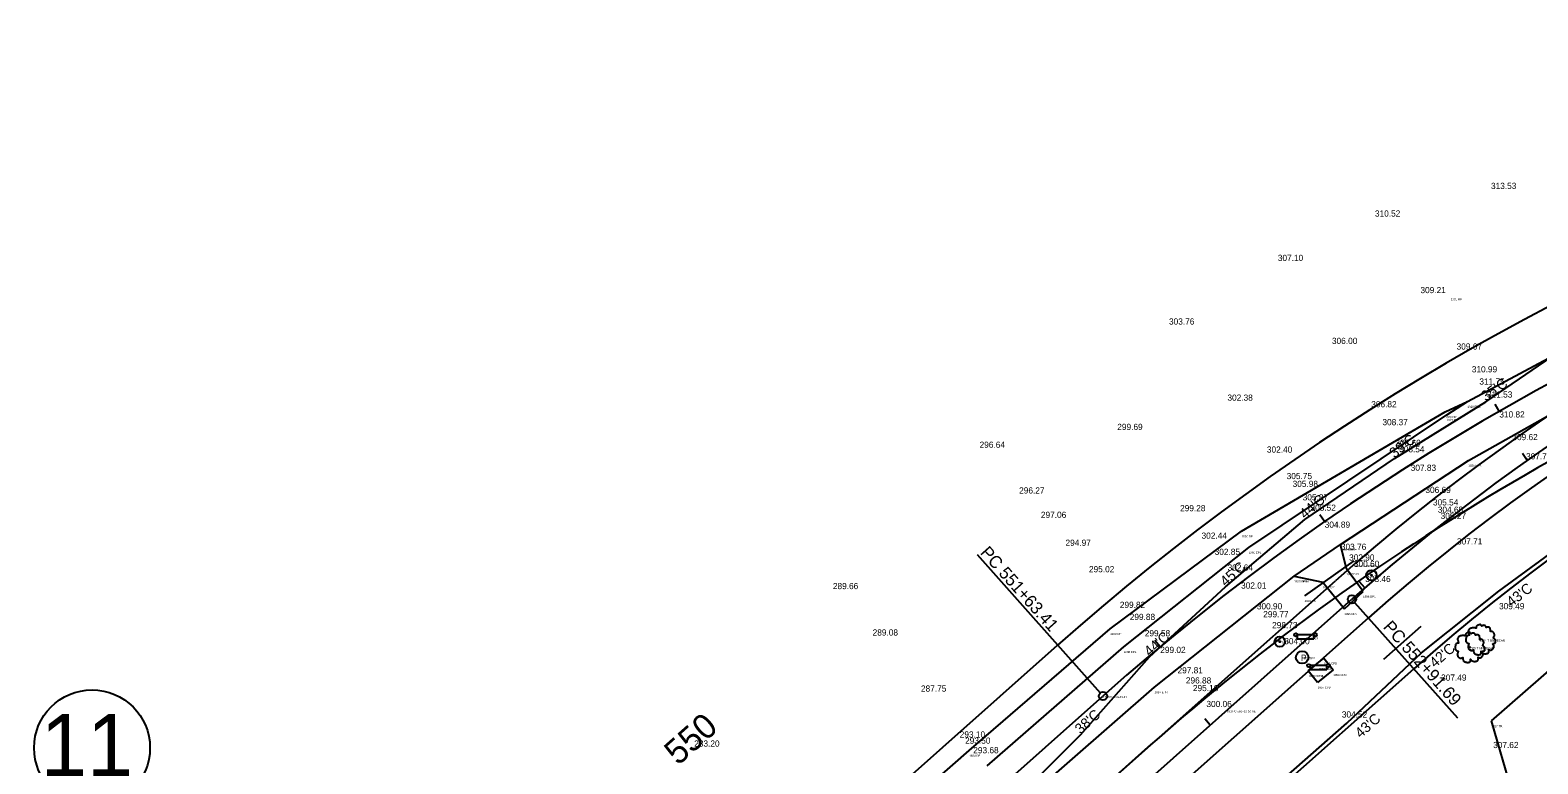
# Model space of a CAD drawing. Extents: x 49683 to 58852, y 49525 to 54803.
# Drawn here: x 55511 to 56241, y 53749 to 54104 of the extents above; entities that cross this region are included whole.
import ezdxf

# ---------------------------------------------------------------- set-up
doc = ezdxf.new("R2010")
doc.units = 0
for name, color, linetype in [('Level 1', 7, 'Continuous'), ('Level 11', 7, 'Continuous'), ('Level 12', 7, 'Continuous'), ('Level 13', 7, 'Continuous'), ('Level 18', 7, 'Continuous'), ('Level 19', 7, 'Continuous'), ('Level 20', 7, 'Continuous'), ('Level 21', 7, 'Continuous'), ('Level 25', 7, 'Continuous'), ('Level 3', 7, 'Continuous'), ('Level 32', 7, 'Continuous'), ('Level 33', 7, 'Continuous'), ('Level 34', 7, 'Continuous'), ('Level 48', 7, 'Continuous'), ('Level 51', 7, 'Continuous'), ('Level 53', 7, 'Continuous'), ('Level 56', 7, 'Continuous'), ('Level 58', 7, 'Continuous'), ('Level 59', 7, 'Continuous'), ('Level 6', 7, 'Continuous'), ('Level 61', 7, 'Continuous'), ('Level 62', 7, 'Continuous'), ('Level 8', 7, 'Continuous'), ('Level 9', 7, 'Continuous')]:
    doc.layers.add(name, color=color, linetype=linetype)

# ---------------------------------------------------------------- blocks, each defined once
blk = doc.blocks.new('IP')
at = {"layer": 'Level 12'}
for radius in [2.5, 0.25]:
    blk.add_circle((0, 0), radius, dxfattribs=at)
blk = doc.blocks.new('TBX')
at = {"layer": 'Level 9'}
for p, q in [((3.99, 1.14), (-4.01, 1.14)), ((-4.01, 1.14), (-4.01, -0.82)), ((3.99, -0.82), (3.99, 1.14)), ((-4.01, -0.82), (3.99, -0.82))]:
    blk.add_line(p, q, dxfattribs=at)
for centre in [(-4.76, 1.14), (4.74, 1.14)]:
    blk.add_circle(centre, 0.75, dxfattribs=at)
blk = doc.blocks.new('TPP')
at = {"layer": 'Level 9'}
blk.add_circle((0, 0), 3, dxfattribs=at)
blk.add_text('P', height=3, dxfattribs=at).set_placement((-0.59, -1.73))
blk = doc.blocks.new('T1')
at = {"layer": 'Level 11'}
for centre, radius in [((0, 0), 0.25), ((-0.01, -0.02), 0.0001)]:
    blk.add_circle(centre, radius, dxfattribs=at)
for points in [[(0.13, 7.17), (-0.17, 7.19), (-0.49, 7.09), (-0.74, 6.99), (-0.97, 6.92), (-1.19, 6.82), (-1.49, 6.64), (-1.72, 6.44), (-1.84, 6.19), (-1.89, 5.97), (-1.94, 5.69), (-1.94, 5.52), (-2.07, 5.49), (-2.22, 5.52), (-2.47, 5.59), (-2.72, 5.59), (-2.97, 5.59), (-3.32, 5.57), (-3.67, 5.57), (-3.94, 5.52), (-4.27, 5.47), (-4.64, 5.34), (-4.99, 5.22), (-5.29, 4.97), (-5.54, 4.49), (-5.67, 4.14), (-5.82, 3.89), (-5.67, 3.44), (-5.49, 3.09), (-5.47, 2.89), (-5.39, 2.47), (-5.29, 2.24), (-5.17, 2.04), (-5.24, 2.02), (-5.62, 1.97), (-5.92, 1.87), (-6.34, 1.64), (-6.57, 1.42), (-6.67, 1.09), (-6.69, 0.75), (-6.79, 0.55), (-6.87, 0.27), (-6.89, 0.2), (-6.94, -0.13), (-6.84, -0.58), (-6.82, -0.93), (-6.69, -1.15), (-6.54, -1.33), (-6.37, -1.58), (-5.97, -1.8), (-5.64, -1.9), (-5.44, -1.93), (-5.62, -2.43), (-5.67, -2.78), (-5.79, -3.18), (-5.79, -3.25), (-5.84, -3.73), (-5.69, -4.05), (-5.62, -4.43), (-5.44, -4.65), (-5.17, -4.95), (-4.84, -5.18), (-4.34, -5.3), (-3.94, -5.28), (-3.37, -5.1), (-3.12, -5.03), (-3.14, -5.2), (-3.12, -5.58), (-3.12, -6), (-2.97, -6.33), (-2.87, -6.6), (-2.72, -6.85), (-2.39, -7.08), (-1.99, -7.15), (-1.57, -7.3), (-1.12, -7.38), (-0.62, -7.4), (-0.02, -7.25), (0.26, -7.13), (0.36, -6.95), (0.56, -6.58), (0.51, -6.35), (0.53, -5.75), (0.63, -5.93), (0.81, -6.28), (1.31, -6.58), (1.71, -6.75), (2.18, -6.9), (2.48, -6.98), (2.96, -6.9), (3.33, -6.83), (3.71, -6.7), (4.01, -6.43), (4.18, -6.15), (4.23, -5.88), (4.31, -5.5), (4.36, -5.33)], [(4.36, -5.33), (4.28, -5.15), (4.23, -4.9), (4.31, -4.93), (4.48, -4.98), (4.75, -5.1), (4.98, -5.18), (5.3, -5.15), (5.58, -5.05), (6.03, -4.78), (6.3, -4.3), (6.58, -3.9), (6.65, -3.58), (6.6, -3.35), (6.58, -2.85), (6.38, -2.6), (6.33, -2.48), (6.23, -2.08), (6.3, -2.03), (6.58, -1.98), (6.95, -1.85), (7.23, -1.73), (7.45, -1.55), (7.53, -1.33), (7.5, -0.93), (7.55, -0.53), (7.48, -0.38), (7.38, -0.23), (7.3, -0.03), (7.15, 0.12), (7.05, 0.27), (6.95, 0.37), (6.83, 0.52), (6.65, 0.65), (6.5, 0.7), (6.45, 0.85), (6.6, 1.04), (6.65, 1.14), (6.68, 1.37), (6.9, 1.72), (6.95, 2.12), (6.9, 2.54), (6.85, 2.82), (6.7, 3.09), (6.5, 3.34), (6.38, 3.52), (6.2, 3.64), (5.88, 3.77), (5.63, 3.82), (5.28, 3.82), (5.08, 3.87), (5.1, 3.92), (5.1, 4.07), (5.1, 4.34), (5.03, 4.79), (4.88, 5.29), (4.88, 5.32), (4.78, 5.57), (4.56, 5.77), (4.38, 5.87), (4.18, 5.99), (3.93, 6.02), (3.63, 6.02), (3.36, 5.97), (3.16, 5.87), (2.98, 5.74), (2.91, 5.89), (2.81, 6.19), (2.76, 6.34), (2.61, 6.52), (2.38, 6.72), (1.93, 6.84), (1.31, 6.77), (1.01, 6.57), (0.86, 6.39), (0.81, 6.52), (0.61, 6.72), (0.51, 6.89), (0.33, 7.02), (0.18, 7.12), (0.08, 7.17)]]:
    blk.add_spline(points, degree=3, dxfattribs=at)

msp = doc.modelspace()

# ---------------------------------------------------------------- linework, layer by layer
at = {"layer": 'Level 1'}
for p, q in [((56222.17, 53919.48), (56220.18, 53922.95)), ((56137.67, 53866.06), (56135.39, 53869.34)), ((55969.5, 53850.14), (56029.09, 53783.1)), ((56058.16, 53805.47), (56055.59, 53808.55)), ((55534.58, 53340.86), (56030.42, 53781.6))]:
    msp.add_line(p, q, dxfattribs=at)
msp.add_circle((56030.42, 53781.6), 2, dxfattribs=at)
msp.add_arc((56791.72, 52925.13), 1145.92, 83.49443, 131.63333, dxfattribs=at)
at = {"layer": 'Level 11'}
for p, q in [((56218.32, 53769.53), (56251.21, 53798.33)), ((56228.2, 53735.68), (56218.32, 53769.53))]:
    msp.add_line(p, q, dxfattribs=at)
at = {"layer": 'Level 13'}
for p, q in [((55512.66, 53365.53), (56008.5, 53806.27)), ((55556.51, 53316.2), (56052.34, 53756.94))]:
    msp.add_line(p, q, dxfattribs=at)
for radius, start in [(1178.92, 86.60044), (1112.92, 108.44495)]:
    msp.add_arc((56791.72, 52925.13), radius, start, 131.63335, dxfattribs=at)
at = {"layer": 'Level 18'}
for p, q in [((56215.63, 53924.12), (56258.38, 53953.39)), ((56171.42, 53896.57), (56215.63, 53924.12)), ((56128.15, 53867.07), (56171.42, 53896.57)), ((56089.77, 53834.41), (56128.15, 53867.07)), ((56221.89, 53832.37), (56260.4, 53860.66)), ((56052.99, 53800.53), (56089.77, 53834.41)), ((56184.48, 53802.58), (56221.89, 53832.37)), ((56019.54, 53762.9), (56052.99, 53800.53)), ((56148.42, 53768.43), (56184.48, 53802.58)), ((56110.9, 53735.37), (56148.42, 53768.43)), ((55984.18, 53727.42), (56019.54, 53762.9))]:
    msp.add_line(p, q, dxfattribs=at)
at = {"layer": 'Level 19'}
for p, q in [((56235.67, 53895.71), (56233.36, 53898.98)), ((56157.09, 53833.94), (56154.45, 53836.95)), ((54181.77, 52078.16), (56150.85, 53828.45)), ((56152.18, 53826.95), (56201.86, 53771.06)), ((56082.32, 53767.53), (56079.66, 53770.52))]:
    msp.add_line(p, q, dxfattribs=at)
msp.add_circle((56150.85, 53828.45), 2, dxfattribs=at)
msp.add_arc((56791.96, 53107.19), 965, 83.49443, 131.63337, dxfattribs=at)
at = {"layer": 'Level 20'}
for p, q in [((55390.95, 53169.04), (56142.88, 53837.41)), ((55400.37, 53145.3), (56158.82, 53819.48))]:
    msp.add_line(p, q, dxfattribs=at)
for radius, start, end in [(977, 84.11358, 131.63331), (953, 83.49443, 131.63337)]:
    msp.add_arc((56791.96, 53107.19), radius, start, end, dxfattribs=at)
at = {"layer": 'Level 25'}
msp.add_circle((55541.4, 53756.52), 28.04, dxfattribs=at)
at = {"layer": 'Level 3'}
for p, q in [((56206.74, 53924.16), (56272.68, 53959.54)), ((56207.19, 53895.72), (56282.12, 53937.76)), ((56196.7, 53917.72), (56206.74, 53924.16)), ((56100.96, 53853.53), (56196.7, 53917.72)), ((56145.4, 53854.95), (56207.19, 53895.72)), ((56122.95, 53839.6), (56145.4, 53854.95)), ((56040.5, 53805.43), (56100.96, 53853.53)), ((56055.41, 53785.96), (56122.95, 53839.6)), ((55974.42, 53747.84), (56040.5, 53805.43)), ((55989.61, 53728.42), (56055.41, 53785.96))]:
    msp.add_line(p, q, dxfattribs=at)
at = {"layer": 'Level 33'}
msp.add_line((55925.36, 53567.81), (56180.75, 53794.81), dxfattribs=at)
msp.add_arc((56791.96, 53107.19), 920, 83.49443, 131.63337, dxfattribs=at)
at = {"layer": 'Level 34'}
msp.add_line((56184.15, 53815.23), (56166.21, 53799.29), dxfattribs=at)
at = {"layer": 'Level 6'}
msp.add_line((56151.85, 53847.05), (56127.97, 53830.15), dxfattribs=at)
at = {"layer": 'Level 8'}
for p, q in [((56196.03, 53919.16), (56206.74, 53924.16)), ((56097.49, 53861.41), (56196.03, 53919.16)), ((56033.94, 53814.18), (56097.49, 53861.41)), ((56148.21, 53843.14), (56145.4, 53854.95)), ((56122.95, 53839.6), (56136.75, 53836.71)), ((56156.24, 53832.22), (56148.21, 53843.14)), ((56136.75, 53836.71), (56147.2, 53823.85)), ((56147.2, 53823.85), (56156.24, 53832.22)), ((55965.73, 53755.18), (56033.94, 53814.18)), ((56129.74, 53793.77), (56137.33, 53799.87)), ((56137.33, 53799.87), (56141.86, 53794.31)), ((56134.27, 53788.21), (56129.74, 53793.77)), ((56141.86, 53794.31), (56134.27, 53788.21)), ((55868.5, 53670.46), (55965.73, 53755.18))]:
    msp.add_line(p, q, dxfattribs=at)

# ---------------------------------------------------------------- block references
at = {"layer": 'Level 11'}
for p in [(56207.69, 53805.29), (56212.86, 53809.01)]:
    msp.add_blockref('T1', p, dxfattribs=at)
at = {"layer": 'Level 12'}
for p in [(56160.27, 53840.1), (56115.99, 53807.93)]:
    msp.add_blockref('IP', p, dxfattribs=at)
at = {"layer": 'Level 9'}
for name, p in [('TBX', (56128.43, 53810.1)), ('TPP', (56126.79, 53800.35)), ('TBX', (56134.73, 53795.2))]:
    msp.add_blockref(name, p, dxfattribs=at)

# ---------------------------------------------------------------- texts
at = {"layer": 'Level 1'}
msp.add_text('PC 551+63.41', height=6, rotation=311.63333, dxfattribs=at).set_placement((55970.75, 53850.82))
at = {"layer": 'Level 19'}
msp.add_text('PC 552+91.69', height=6, rotation=311.63336, dxfattribs=at).set_placement((56165.63, 53814.83))
at = {"layer": 'Level 21'}
msp.add_text('550', height=12, rotation=41.63333, dxfattribs=at).set_placement((55824.91, 53747.63))
at = {"layer": 'Level 25'}
msp.add_text('11', height=30, dxfattribs=at).set_placement((55516.61, 53742.9))
at = {"layer": 'Level 32'}
for s, p in [('313.53', (56218.15, 54027.12)), ('310.52', (56162.01, 54013.76)), ('307.10', (56115.02, 53992.26)), ('309.21', (56184.01, 53976.69)), ('303.76', (56062.38, 53961.47)), ('306.00', (56141.21, 53952.08)), ('309.67', (56201.5, 53949.37)), ('310.99', (56208.86, 53938.34)), ('311.75', (56212.51, 53932.41)), ('302.38', (56090.65, 53924.59)), ('311.53', (56216.21, 53926.14)), ('306.82', (56160.21, 53921.39)), ('299.69', (56037.36, 53910.43)), ('308.37', (56165.63, 53912.73)), ('310.82', (56222.17, 53916.48)), ('308.69', (56171.89, 53902.72)), ('309.62', (56228.48, 53905.51)), ('296.64', (55970.75, 53901.8)), ('302.40', (56109.74, 53899.47)), ('308.54', (56173.7, 53899.62)), ('307.73', (56235.09, 53896.19)), ('307.83', (56179.32, 53890.65)), ('305.75', (56119.3, 53886.64)), ('305.98', (56122.18, 53882.84)), ('296.27', (55989.89, 53879.67)), ('305.87', (56127.05, 53876.34)), ('306.69', (56186.41, 53879.93)), ('305.54', (56190.06, 53873.89)), ('297.06', (56000.41, 53867.86)), ('299.28', (56067.75, 53871.08)), ('305.52', (56130.81, 53871.31)), ('304.60', (56192.41, 53870.35)), ('305.27', (56193.79, 53867.33)), ('304.89', (56137.71, 53863.1)), ('294.97', (56012.31, 53854.35)), ('302.44', (56078.12, 53857.77)), ('303.76', (56145.53, 53852.39)), ('307.71', (56201.69, 53855)), ('302.85', (56084.47, 53849.95)), ('302.90', (56149.51, 53847.19)), ('300.60', (56151.83, 53844.12)), ('295.02', (56023.66, 53841.54)), ('302.64', (56090.72, 53842.31)), ('303.46', (56157.32, 53836.8)), ('289.66', (55899.78, 53833.37)), ('302.01', (56097.25, 53833.63)), ('299.82', (56038.59, 53824.28)), ('300.90', (56104.87, 53823.58)), ('309.49', (56222.04, 53823.63)), ('299.88', (56043.39, 53818.43)), ('299.77', (56107.95, 53819.72)), ('289.08', (55919.01, 53810.89)), ('299.58', (56050.66, 53810.52)), ('298.73', (56112.27, 53814.46)), ('299.02', (56058.15, 53802.47)), ('304.00', (56118.14, 53806.71)), ('297.81', (56066.5, 53792.58)), ('296.88', (56070.54, 53787.69)), ('307.49', (56194.01, 53789.04)), ('287.75', (55942.39, 53783.73)), ('295.16', (56073.94, 53783.98)), ('300.06', (56080.48, 53776.26)), ('304.52', (56145.98, 53771.2)), ('283.20', (55832.71, 53757.11)), ('293.10', (55961.15, 53761.5)), ('293.50', (55963.74, 53758.52)), ('307.62', (56219.18, 53756.4)), ('293.68', (55967.69, 53753.89))]:
    msp.add_text(s, height=3, dxfattribs=at).set_placement(p)
at = {"layer": 'Level 48'}
for s, rotation, p in [("35'C", 35.20258, (56215.63, 53924.12)), ("39'C", 38.17131, (56171.42, 53896.57)), ("44'C", 41.13996, (56128.15, 53867.07)), ("45'C", 41.63339, (56089.77, 53834.41)), ("43'C", 38.17127, (56228.07, 53824.5)), ("44'C", 41.63335, (56052.99, 53800.53)), ("42'C", 41.13999, (56191.06, 53795.05)), ("38'C", 41.63336, (56019.54, 53762.9)), ("43'C", 41.63336, (56155.06, 53760.96))]:
    msp.add_text(s, height=5, rotation=rotation, dxfattribs=at).set_placement(p)
at = {"layer": 'Level 51'}
for s, p in [('173 PC 551+63.41 ', (56030.42, 53780.6)), ('181 PC 552+10.88 RE ', (56090.45, 53773.76))]:
    msp.add_text(s, height=1, dxfattribs=at).set_placement(p)
at = {"layer": 'Level 53'}
for s, p in [('1930 EPL ', (56206.74, 53921.16)), ('1927 EPL ', (56196.7, 53914.72)), ('1926 EPR ', (56207.19, 53892.72)), ('1891 EPL ', (56100.96, 53850.53)), ('1899 EPR ', (56145.4, 53851.95)), ('1892 EPR ', (56122.95, 53836.6)), ('1888 EPL ', (56040.5, 53802.43)), ('1887 EPR ', (56055.41, 53782.96))]:
    msp.add_text(s, height=1, dxfattribs=at).set_placement(p)
at = {"layer": 'Level 56'}
for s, p in [('1900 PA 18IN RC ', (56151.85, 53844.05)), ('1901 PB ', (56127.97, 53827.15))]:
    msp.add_text(s, height=1, dxfattribs=at).set_placement(p)
at = {"layer": 'Level 58'}
for s, p in [('1929 DPB ', (56206.74, 53921.16)), ('1928 DP ', (56196.03, 53916.16)), ('1890 DP ', (56097.49, 53858.41)), ('1898 DP1B ', (56145.4, 53851.95)), ('1897 DP1 ', (56148.21, 53840.14)), ('1893 DP1A ', (56122.95, 53836.6)), ('1894 DP1 ', (56136.75, 53833.71)), ('1896 DP1 ', (56156.24, 53829.22)), ('1895 DP1 ', (56147.2, 53820.85)), ('1889 DP ', (56033.94, 53811.18)), ('1905 CPD ', (56137.33, 53796.87)), ('1904 CPDA ', (56129.74, 53790.77)), ('1908 CPDB ', (56129.74, 53790.77)), ('1906 CPD ', (56141.86, 53791.31)), ('1907 CPD ', (56134.27, 53785.21)), ('1884 DP ', (55965.73, 53752.18))]:
    msp.add_text(s, height=1, dxfattribs=at).set_placement(p)
at = {"layer": 'Level 59'}
for s, p in [('1902 TBX ', (56128.43, 53809.1)), ('1903 TPP ', (56126.79, 53799.35)), ('1909 TBX ', (56134.73, 53794.2))]:
    msp.add_text(s, height=1, dxfattribs=at).set_placement(p)
at = {"layer": 'Level 61'}
for s, p in [('1931 HA ', (56198.67, 53973.27)), ('1925 T 8IN PECAN ', (56207.69, 53804.29)), ('1924 T 8IN PECAN ', (56212.86, 53808.01)), ('1917 TR ', (56218.32, 53766.53))]:
    msp.add_text(s, height=1, dxfattribs=at).set_placement(p)
at = {"layer": 'Level 62'}
for s, p in [('1715 IP ', (56160.27, 53839.1)), ('1716 IP ', (56115.99, 53806.93))]:
    msp.add_text(s, height=1, dxfattribs=at).set_placement(p)

doc.saveas('drawing.dxf')
